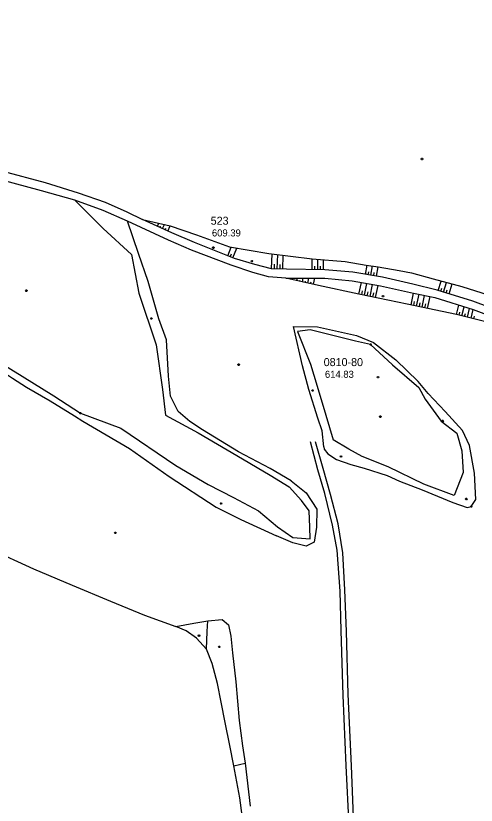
# Model space of a CAD drawing. Extents: x -664960 to -662754, y -993849 to -991145.
# Drawn here: x -663507.3 to -663311.8, y -991825.9 to -991490.5 of the extents above; entities that cross this region are included whole.
import ezdxf

# ---------------------------------------------------------------- set-up
doc = ezdxf.new("R2010")
doc.units = 0
for name, color, linetype in [('Vrstva 1', 7, 'Continuous'), ('Vrstva 13', 7, 'Continuous'), ('Vrstva 18', 7, 'Continuous'), ('Vrstva 27', 7, 'Continuous'), ('Vrstva 33', 7, 'Continuous'), ('Vrstva 63', 7, 'Continuous'), ('Vrstva 8', 7, 'Continuous')]:
    doc.layers.add(name, color=color, linetype=linetype)

msp = doc.modelspace()

# ---------------------------------------------------------------- linework, layer by layer
at = {"layer": 'Vrstva 13'}
for points in [[(-663334.696, -991551.021), (-663334.516, -991551.321), (-663334.696, -991551.621), (-663335.056, -991551.621), (-663335.236, -991551.321), (-663335.056, -991551.021), (-663334.696, -991551.021)], [(-663406.905, -991594.422), (-663406.725, -991594.722), (-663406.905, -991595.022), (-663407.265, -991595.022), (-663407.445, -991594.722), (-663407.265, -991594.422), (-663406.905, -991594.422)], [(-663502.637, -991606.96), (-663502.457, -991607.26), (-663502.637, -991607.56), (-663502.997, -991607.56), (-663503.177, -991607.26), (-663502.997, -991606.96), (-663502.637, -991606.96)], [(-663351.266, -991609.289), (-663351.086, -991609.589), (-663351.266, -991609.889), (-663351.626, -991609.889), (-663351.806, -991609.589), (-663351.626, -991609.289), (-663351.266, -991609.289)], [(-663449.546, -991618.803), (-663449.366, -991619.103), (-663449.546, -991619.403), (-663449.906, -991619.403), (-663450.086, -991619.103), (-663449.906, -991618.803), (-663449.546, -991618.803)], [(-663412.5, -991638.415), (-663412.32, -991638.715), (-663412.5, -991639.015), (-663412.86, -991639.015), (-663413.04, -991638.715), (-663412.86, -991638.415), (-663412.5, -991638.415)], [(-663381.161, -991649.406), (-663380.981, -991649.706), (-663381.161, -991650.006), (-663381.521, -991650.006), (-663381.701, -991649.706), (-663381.521, -991649.406), (-663381.161, -991649.406)], [(-663352.337, -991660.505), (-663352.157, -991660.805), (-663352.337, -991661.105), (-663352.697, -991661.105), (-663352.877, -991660.805), (-663352.697, -991660.505), (-663352.337, -991660.505)], [(-663325.961, -991662.344), (-663325.781, -991662.644), (-663325.961, -991662.944), (-663326.321, -991662.944), (-663326.501, -991662.644), (-663326.321, -991662.344), (-663325.961, -991662.344)], [(-663369.086, -991677.437), (-663368.906, -991677.737), (-663369.086, -991678.037), (-663369.446, -991678.037), (-663369.626, -991677.737), (-663369.446, -991677.437), (-663369.086, -991677.437)], [(-663315.899, -991695.496), (-663315.719, -991695.796), (-663315.899, -991696.096), (-663316.259, -991696.096), (-663316.439, -991695.796), (-663316.259, -991695.496), (-663315.899, -991695.496)], [(-663419.974, -991697.383), (-663419.794, -991697.683), (-663419.974, -991697.983), (-663420.334, -991697.983), (-663420.514, -991697.683), (-663420.334, -991697.383), (-663419.974, -991697.383)], [(-663464.868, -991709.822), (-663464.688, -991710.122), (-663464.868, -991710.422), (-663465.228, -991710.422), (-663465.408, -991710.122), (-663465.228, -991709.822), (-663464.868, -991709.822)], [(-663429.384, -991753.581), (-663429.204, -991753.881), (-663429.384, -991754.181), (-663429.744, -991754.181), (-663429.924, -991753.881), (-663429.744, -991753.581), (-663429.384, -991753.581)]]:
    msp.add_lwpolyline(points, dxfattribs=at)
at = {"layer": 'Vrstva 18'}
for points in [[(-663356.529, -991629.802), (-663356.349, -991630.102), (-663356.529, -991630.402), (-663356.889, -991630.402), (-663357.069, -991630.102), (-663356.889, -991629.802), (-663356.529, -991629.802)], [(-663313.798, -991698.701), (-663313.618, -991699.001), (-663313.798, -991699.301), (-663314.158, -991699.301), (-663314.338, -991699.001), (-663314.158, -991698.701), (-663313.798, -991698.701)]]:
    msp.add_lwpolyline(points, dxfattribs=at)
at = {"layer": 'Vrstva 27'}
for points in [[(-663743.58, -991388.419), (-663729.844, -991404.645), (-663713.114, -991418.331), (-663678.355, -991443.741), (-663655.175, -991461.78), (-663640.263, -991473.397), (-663617.672, -991490.323), (-663595.769, -991506.951), (-663579.337, -991518.755), (-663559.944, -991534.662), (-663551.457, -991541.221), (-663543.359, -991545.874), (-663534.399, -991549.773), (-663524.913, -991553.126), (-663512.846, -991556.521), (-663494.937, -991561.373), (-663480.847, -991565.652), (-663469.411, -991569.732), (-663460.126, -991573.712), (-663453.502, -991577.004)], [(-663392.708, -991601.995), (-663400.049, -991601.363), (-663406.753, -991599.585), (-663415.923, -991596.415), (-663432.77, -991590.116), (-663442.566, -991585.813), (-663459.978, -991577.759), (-663470.267, -991573.243), (-663482.264, -991568.867), (-663496.396, -991564.917), (-663513.654, -991560.159), (-663526.11, -991556.319), (-663535.27, -991553.444), (-663544.844, -991548.86), (-663553.272, -991543.904), (-663561.986, -991538.065), (-663566.199, -991534.736), (-663576.928, -991526.255), (-663582.099, -991521.945), (-663598.014, -991510.037), (-663620.559, -991493.213), (-663642.167, -991476.69), (-663657.561, -991464.555), (-663680.78, -991446.59)], [(-663365.766, -991834.788), (-663367.061, -991809.084), (-663368.33, -991779.29), (-663369.12, -991751.685), (-663369.628, -991734.909), (-663370.817, -991717.576), (-663372.9, -991706.955), (-663376.186, -991693.498), (-663379.052, -991683.469), (-663382.164, -991671.555)], [(-663361.412, -991910.643), (-663361.623, -991888.2), (-663362.818, -991861.554), (-663363.863, -991834.538), (-663364.841, -991809.195), (-663366.195, -991778.792), (-663366.957, -991752.07), (-663367.559, -991734.45), (-663368.487, -991718.674), (-663370.521, -991706.328), (-663373.676, -991693.914), (-663376.846, -991682.816), (-663380.136, -991671.455)]]:
    msp.add_lwpolyline(points, dxfattribs=at)
at = {"layer": 'Vrstva 33'}
msp.add_lwpolyline([(-663420.777, -991758.299), (-663420.597, -991758.599), (-663420.777, -991758.899), (-663421.137, -991758.899), (-663421.317, -991758.599), (-663421.137, -991758.299), (-663420.777, -991758.299)], dxfattribs=at)
at = {"layer": 'Vrstva 63'}
for p, q in [((-663447.196, -991579.921), (-663446.585, -991578.598)), ((-663445.018, -991580.928), (-663444.195, -991579.149)), ((-663446.107, -991580.424), (-663445.868, -991579.908)), ((-663443.929, -991581.432), (-663443.62, -991580.763)), ((-663442.84, -991581.936), (-663441.805, -991579.699)), ((-663417.371, -991592.469), (-663415.853, -991588.749)), ((-663415.149, -991593.376), (-663413.428, -991589.158)), ((-663416.26, -991592.922), (-663415.721, -991591.6)), ((-663398.734, -991598.005), (-663398.536, -991591.602)), ((-663396.335, -991598.079), (-663396.144, -991591.894)), ((-663393.937, -991598.154), (-663393.752, -991592.185)), ((-663397.535, -991598.042), (-663397.47, -991595.946)), ((-663381.536, -991598.304), (-663381.493, -991593.68)), ((-663379.136, -991598.327), (-663379.095, -991593.896)), ((-663376.737, -991598.349), (-663376.697, -991594.113)), ((-663395.136, -991598.116), (-663395.073, -991596.093)), ((-663380.336, -991598.315), (-663380.322, -991596.808)), ((-663377.936, -991598.338), (-663377.923, -991596.895)), ((-663358.889, -991600.339), (-663358.216, -991596.454)), ((-663357.706, -991600.544), (-663357.48, -991599.237)), ((-663356.524, -991600.748), (-663355.838, -991596.787)), ((-663354.159, -991601.158), (-663353.46, -991597.119)), ((-663392.708, -991601.995), (-663392.708, -991601.995)), ((-663391.535, -991602.25), (-663391.516, -991602.163)), ((-663390.363, -991602.506), (-663390.249, -991601.981)), ((-663389.191, -991602.761), (-663389.133, -991602.499)), ((-663388.018, -991603.017), (-663387.789, -991601.968)), ((-663385.673, -991603.528), (-663385.33, -991601.954)), ((-663383.328, -991604.039), (-663382.871, -991601.941)), ((-663380.983, -991604.55), (-663380.412, -991601.927)), ((-663355.342, -991600.953), (-663355.111, -991599.621)), ((-663386.846, -991603.272), (-663386.75, -991602.836)), ((-663384.501, -991603.783), (-663384.367, -991603.172)), ((-663382.156, -991604.294), (-663381.984, -991603.508)), ((-663361.614, -991608.773), (-663360.581, -991603.74)), ((-663359.263, -991609.255), (-663358.218, -991604.164)), ((-663356.912, -991609.738), (-663355.855, -991604.587)), ((-663354.561, -991610.22), (-663353.492, -991605.011)), ((-663327.983, -991607.236), (-663326.727, -991603.183)), ((-663325.691, -991607.947), (-663324.401, -991603.786)), ((-663323.398, -991608.657), (-663322.075, -991604.388)), ((-663360.439, -991609.014), (-663360.093, -991607.328)), ((-663358.088, -991609.497), (-663357.738, -991607.791)), ((-663355.737, -991609.979), (-663355.383, -991608.254)), ((-663339.51, -991613.32), (-663338.442, -991608.275)), ((-663337.162, -991613.817), (-663336.097, -991608.787)), ((-663334.814, -991614.314), (-663333.752, -991609.3)), ((-663326.837, -991607.591), (-663326.413, -991606.224)), ((-663324.544, -991608.302), (-663324.109, -991606.898)), ((-663338.336, -991613.569), (-663337.98, -991611.891)), ((-663335.988, -991614.066), (-663335.634, -991612.393)), ((-663332.466, -991614.811), (-663331.408, -991609.813)), ((-663333.64, -991614.563), (-663333.287, -991612.896)), ((-663320.255, -991617.396), (-663319.275, -991613.419)), ((-663317.925, -991617.97), (-663316.979, -991614.136)), ((-663315.595, -991618.545), (-663314.684, -991614.853)), ((-663313.992, -991618.94), (-663313.105, -991615.345)), ((-663319.09, -991617.683), (-663318.769, -991616.383)), ((-663316.76, -991618.258), (-663316.451, -991617.004)), ((-663312.827, -991619.228), (-663312.542, -991618.071)), ((-663414.773, -991809.18), (-663409.93, -991808.068))]:
    msp.add_line(p, q, dxfattribs=at)
for points in [[(-663482.264, -991568.867), (-663470.212, -991580.865), (-663458.281, -991591.843), (-663455.04, -991608.397), (-663447.781, -991630.298), (-663445.032, -991649.223), (-663443.769, -991660.181), (-663429.925, -991667.751), (-663413.417, -991677.3), (-663399.332, -991685.696), (-663391.28, -991690.679)], [(-663390.439, -991688.079), (-663399.274, -991682.797), (-663412.74, -991675.825), (-663428.102, -991666.476), (-663433.5, -991662.917), (-663438.375, -991658.595), (-663441.68, -991652.038), (-663442.498, -991643.553), (-663443.306, -991628.171), (-663446.558, -991619.253), (-663451.177, -991603.359), (-663455.269, -991591.496), (-663459.978, -991577.759)], [(-663453.502, -991577.004), (-663441.805, -991579.699), (-663430.555, -991583.545), (-663416.622, -991588.619), (-663399.958, -991591.429), (-663381.493, -991593.68), (-663367.488, -991594.945), (-663358.618, -991596.398), (-663353.46, -991597.119), (-663344.525, -991598.685), (-663339.316, -991599.675), (-663330.111, -991602.308), (-663317.895, -991605.469), (-663304.149, -991609.928)], [(-663306.055, -991614.384), (-663313.272, -991611.795), (-663328.356, -991607.121), (-663338.709, -991604.536), (-663351.645, -991601.593), (-663364.25, -991599.411), (-663376.111, -991598.355), (-663392.35, -991598.203), (-663398.734, -991598.005), (-663405.856, -991596.163), (-663414.539, -991593.624), (-663431.406, -991586.741), (-663441.056, -991582.76), (-663453.502, -991577.004)], [(-663392.708, -991601.995), (-663376.181, -991601.904), (-663364.511, -991603.034), (-663352.434, -991605.201), (-663338.442, -991608.275), (-663329.464, -991610.238), (-663313.105, -991615.345), (-663307.435, -991617.382), (-663290.206, -991623.365), (-663277.294, -991628.432), (-663290.422, -991624.866), (-663310.079, -991619.905), (-663320.255, -991617.396), (-663341.118, -991612.98), (-663361.614, -991608.773), (-663378.846, -991605.015), (-663392.708, -991601.995)], [(-663548.116, -991616.856), (-663530.675, -991627.572), (-663517.442, -991635.824), (-663504.686, -991643.622), (-663491.143, -991652.018), (-663479.888, -991659.272)], [(-663545.518, -991622.837), (-663542.3, -991624.235), (-663531.959, -991629.738), (-663518.182, -991638.283), (-663508.772, -991644.5), (-663502.811, -991648.258), (-663492.706, -991654.085), (-663482.346, -991660.443)], [(-663376.607, -991673.636), (-663377.196, -991666.82), (-663379.102, -991661.449), (-663382.93, -991649.298), (-663385.667, -991639.213), (-663389.37, -991622.468), (-663379.207, -991622.625), (-663362.622, -991626.376), (-663355.422, -991629.315), (-663345.927, -991636.595), (-663336.449, -991645.919)], [(-663347.413, -991638.826), (-663356.709, -991630.102), (-663363.039, -991628.686), (-663382.404, -991623.943), (-663387.675, -991624.56), (-663382.24, -991638.533), (-663379.376, -991647.917), (-663375.724, -991660.227), (-663372.606, -991670.701)], [(-663347.413, -991638.826), (-663336.177, -991648.362), (-663333.51, -991653.389)], [(-663315.648, -991699.344), (-663313.978, -991699.001), (-663312.037, -991696.007), (-663312.548, -991684.858), (-663314.654, -991673.053), (-663317.676, -991666.675), (-663325.057, -991658.562), (-663332.237, -991650.917), (-663336.449, -991645.919)], [(-663333.51, -991653.389), (-663326.763, -991662.791), (-663320.085, -991667.887), (-663317.97, -991675.37), (-663317.354, -991684.515)], [(-663479.708, -991658.972), (-663479.528, -991659.272), (-663479.708, -991659.572), (-663480.068, -991659.572), (-663480.248, -991659.272), (-663480.068, -991658.972), (-663479.708, -991658.972)], [(-663479.888, -991659.272), (-663462.786, -991665.65), (-663439.344, -991681.494), (-663425.646, -991689.698), (-663414.964, -991695.17), (-663404.326, -991700.87), (-663396.218, -991707.59), (-663389.765, -991712.179), (-663382.382, -991712.721), (-663382.54, -991707.824), (-663382.81, -991700.851), (-663385.998, -991696.409), (-663391.28, -991690.679)], [(-663482.346, -991660.443), (-663478.85, -991662.68), (-663459.07, -991674.4), (-663442.17, -991686.19), (-663422.26, -991699.29), (-663411.75, -991704.51), (-663396.61, -991711.5)], [(-663317.354, -991684.515), (-663321.192, -991694.265), (-663334.054, -991689.467), (-663349.236, -991682.089), (-663360.295, -991677.737), (-663365.923, -991674.566), (-663372.606, -991670.701)], [(-663376.607, -991673.636), (-663376.35, -991674.56), (-663374.818, -991676.608), (-663371.149, -991679.064), (-663365.062, -991681.131), (-663359.361, -991682.706), (-663349.647, -991685.742), (-663344.473, -991688.254), (-663334.788, -991691.946), (-663321.746, -991697.263), (-663315.648, -991699.344)], [(-663390.439, -991688.079), (-663383.988, -991693.186), (-663379.577, -991700.185), (-663379.719, -991707.763), (-663380.641, -991714.108), (-663384.035, -991715.784), (-663389.759, -991714.432), (-663396.61, -991711.5)], [(-663534.725, -991710.824), (-663518.545, -991717.031), (-663499.888, -991725.479), (-663483.464, -991732.469), (-663467.097, -991739.167), (-663452.683, -991745.176), (-663439.395, -991749.905), (-663431.74, -991748.578), (-663425.793, -991747.578), (-663419.769, -991746.977), (-663417.071, -991749.271), (-663415.983, -991754.087), (-663415.339, -991761.23), (-663413.882, -991773.433), (-663412.468, -991789.98), (-663411.061, -991800.626), (-663409.93, -991808.068), (-663407.784, -991826.362)], [(-663410.58, -991835.673), (-663412.273, -991822.802), (-663414.773, -991809.18), (-663416.414, -991800.59), (-663418.397, -991790.72), (-663420.094, -991782.07), (-663421.664, -991774.189), (-663423.979, -991765.713), (-663426.304, -991759.534), (-663430.573, -991754.923), (-663435.02, -991751.821), (-663439.395, -991749.905)], [(-663426.304, -991759.534), (-663426.07, -991752.057), (-663425.793, -991747.578)]]:
    msp.add_lwpolyline(points, dxfattribs=at)
at = {"layer": 'Vrstva 8'}
for points in [[(-663423.32, -991588.69), (-663423.14, -991588.99), (-663423.32, -991589.29), (-663423.68, -991589.29), (-663423.86, -991588.99), (-663423.68, -991588.69), (-663423.32, -991588.69)], [(-663353.33, -991643.78), (-663353.15, -991644.08), (-663353.33, -991644.38), (-663353.69, -991644.38), (-663353.87, -991644.08), (-663353.69, -991643.78), (-663353.33, -991643.78)]]:
    msp.add_lwpolyline(points, dxfattribs=at)

# ---------------------------------------------------------------- texts
at = {"layer": 'Vrstva 1'}
for s, p in [('523', (-663424.588, -991579.258)), ('0810-80', (-663376.603, -991639.325))]:
    msp.add_text(s, height=3.4, dxfattribs=at).set_placement(p)
at = {"layer": 'Vrstva 63'}
for s, p in [('609.39', (-663424.065, -991584.238)), ('614.83', (-663376.079, -991644.305))]:
    msp.add_text(s, height=3, dxfattribs=at).set_placement(p)

doc.saveas('drawing.dxf')
